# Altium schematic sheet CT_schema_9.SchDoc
size 287 x 160 mm
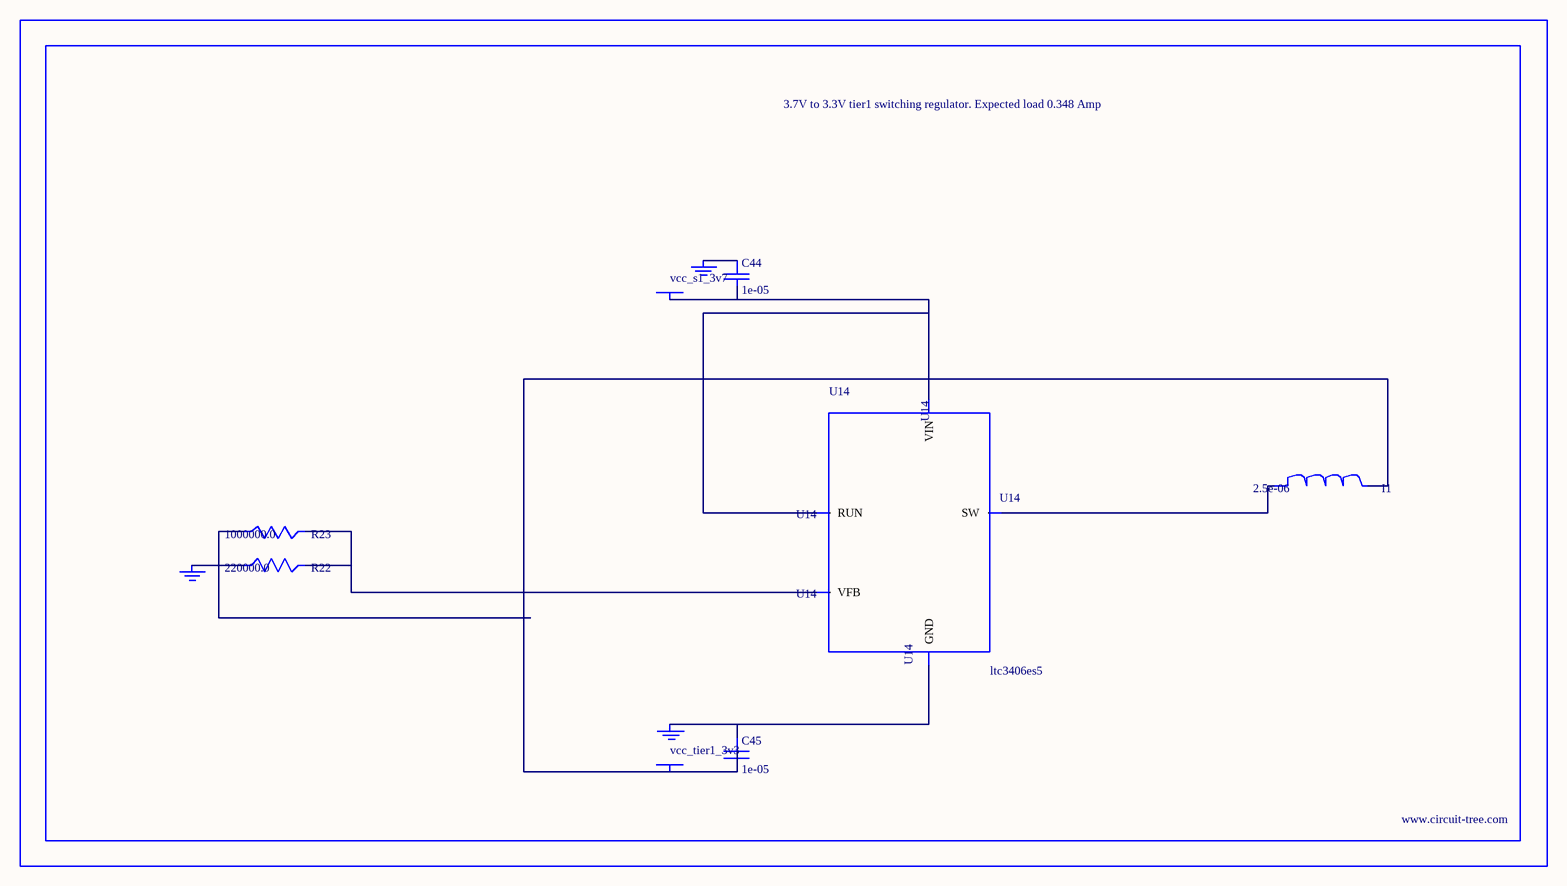
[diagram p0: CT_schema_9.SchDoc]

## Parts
BORDER8  (no value)
C44  1e-05  [C0805]
C45  1e-05  [C0805]
GND_INSTANCE_8_0  (no value)
GND_INSTANCE_8_1  (no value)
GND_INSTANCE_8_2  (no value)
I1  2.5e-06  [DR1040]
POWER_INSTANCE_8_0  vcc_tier1_3v3
POWER_INSTANCE_8_1  vcc_s1_3v7
R22  220000.0  [R0603]
R23  1000000.0  [R0603]
U14  ltc3406es5  [TSOT-23-5]

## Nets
NetC44_1: C44.1 GND_INSTANCE_8_1.0(GND)
NetC44_2: C44.2 POWER_INSTANCE_8_1.0(PWR) U14.1(RUN) U14.4(VIN)
NetC45_1: C45.1 GND_INSTANCE_8_0.0(GND) U14.2(GND)
NetC45_2: C45.2 I1.2 POWER_INSTANCE_8_0.0(PWR) R23.1
NetGND_INSTANCE_8_2_0: GND_INSTANCE_8_2.0(GND) R22.1
NetI1_1: I1.1 U14.3(SW)
NetR22_2: R22.2 R23.2 U14.5(VFB)

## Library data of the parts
BORDER8 = BORDER_PAGE8
C44 C45 = C0805C106K8RACTU
GND_INSTANCE_8_0-GND_INSTANCE_8_2 = GND
I1 = DR1040-2R5-R
POWER_INSTANCE_8_0 POWER_INSTANCE_8_1 = PWR
R22 = RC0603JR-07220KL
R23 = RC0603JR-071ML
